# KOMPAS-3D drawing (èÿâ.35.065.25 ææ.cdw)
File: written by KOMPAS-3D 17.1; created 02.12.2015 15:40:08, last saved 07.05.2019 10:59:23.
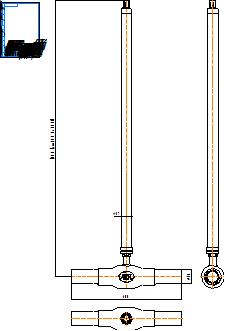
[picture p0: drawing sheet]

Sheet 1: A4, portrait

Title block, sheet 1: name: КШГ.35.065.25 СС; material: Внимание! Данный продукт является объектом авторского права ООО «Торговый Дом АДЛ». / Запрещается изменение, копирование, распространение / (в том числе путем копирования на другие сайты и ресурсы в Интернете) / или любое иное использование информации и объектов без предварительного / согласия правообладателя (ООО «Торговый Дом АДЛ»).; sheets: 1; organisation: ООО "Торговый дом АДЛ"; sheet format: A4; stored path: C:\Users\kka\KOMPAS_Work\Модели кранов для исследований\DN50\С удлинением\КШГ.32.050.40 СС ГЧ _ Шаровой кран БИВАЛ Ду50 Ру4 МПа редуцированный под приварку, с удлинением штока H=1100.cdw; drawn by: Климкович К.А.; drawn by, date: 02.12.15

Views: Вид 1, Проекционный вид 2
Referenced files in C:\Users\kka\KOMPAS_Work\Модели кранов для исследований\DN80\С удлинением\: КШТ.22.080.25 СС.a3d, КШГ.35.065.25 СС.a3d!КШГ.45.065.10 СС!Деталь (локальная).m3d
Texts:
  Klimkovich
  ADL
  (от 297 до 5000)
Dimensions and other numbers on the sheet: 600; 1500; 76; 57; 1:1; 1; 02.12.15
